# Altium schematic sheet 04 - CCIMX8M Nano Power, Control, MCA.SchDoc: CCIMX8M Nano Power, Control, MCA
size A3; PageSetup: Record=PageOptions¦CenterHorizontal=True¦CenterVertical=True¦PrintScale=0.70¦XCorrection=1.00¦YCorrection=1.00¦PrintKind=0¦BorderSize=5000000¦LeftOffset=0¦BottomOffset=0¦Orientation=2¦PaperLength=4200¦PaperWidth=2970¦Scale=100¦PaperSource=7¦PrintQuality=600¦MediaType=1¦DitherType=10¦PaperKind=A4¦PrintScaleMode=1; Author: Juan Anzola; SheetNumber: 4; SheetTotal: 21
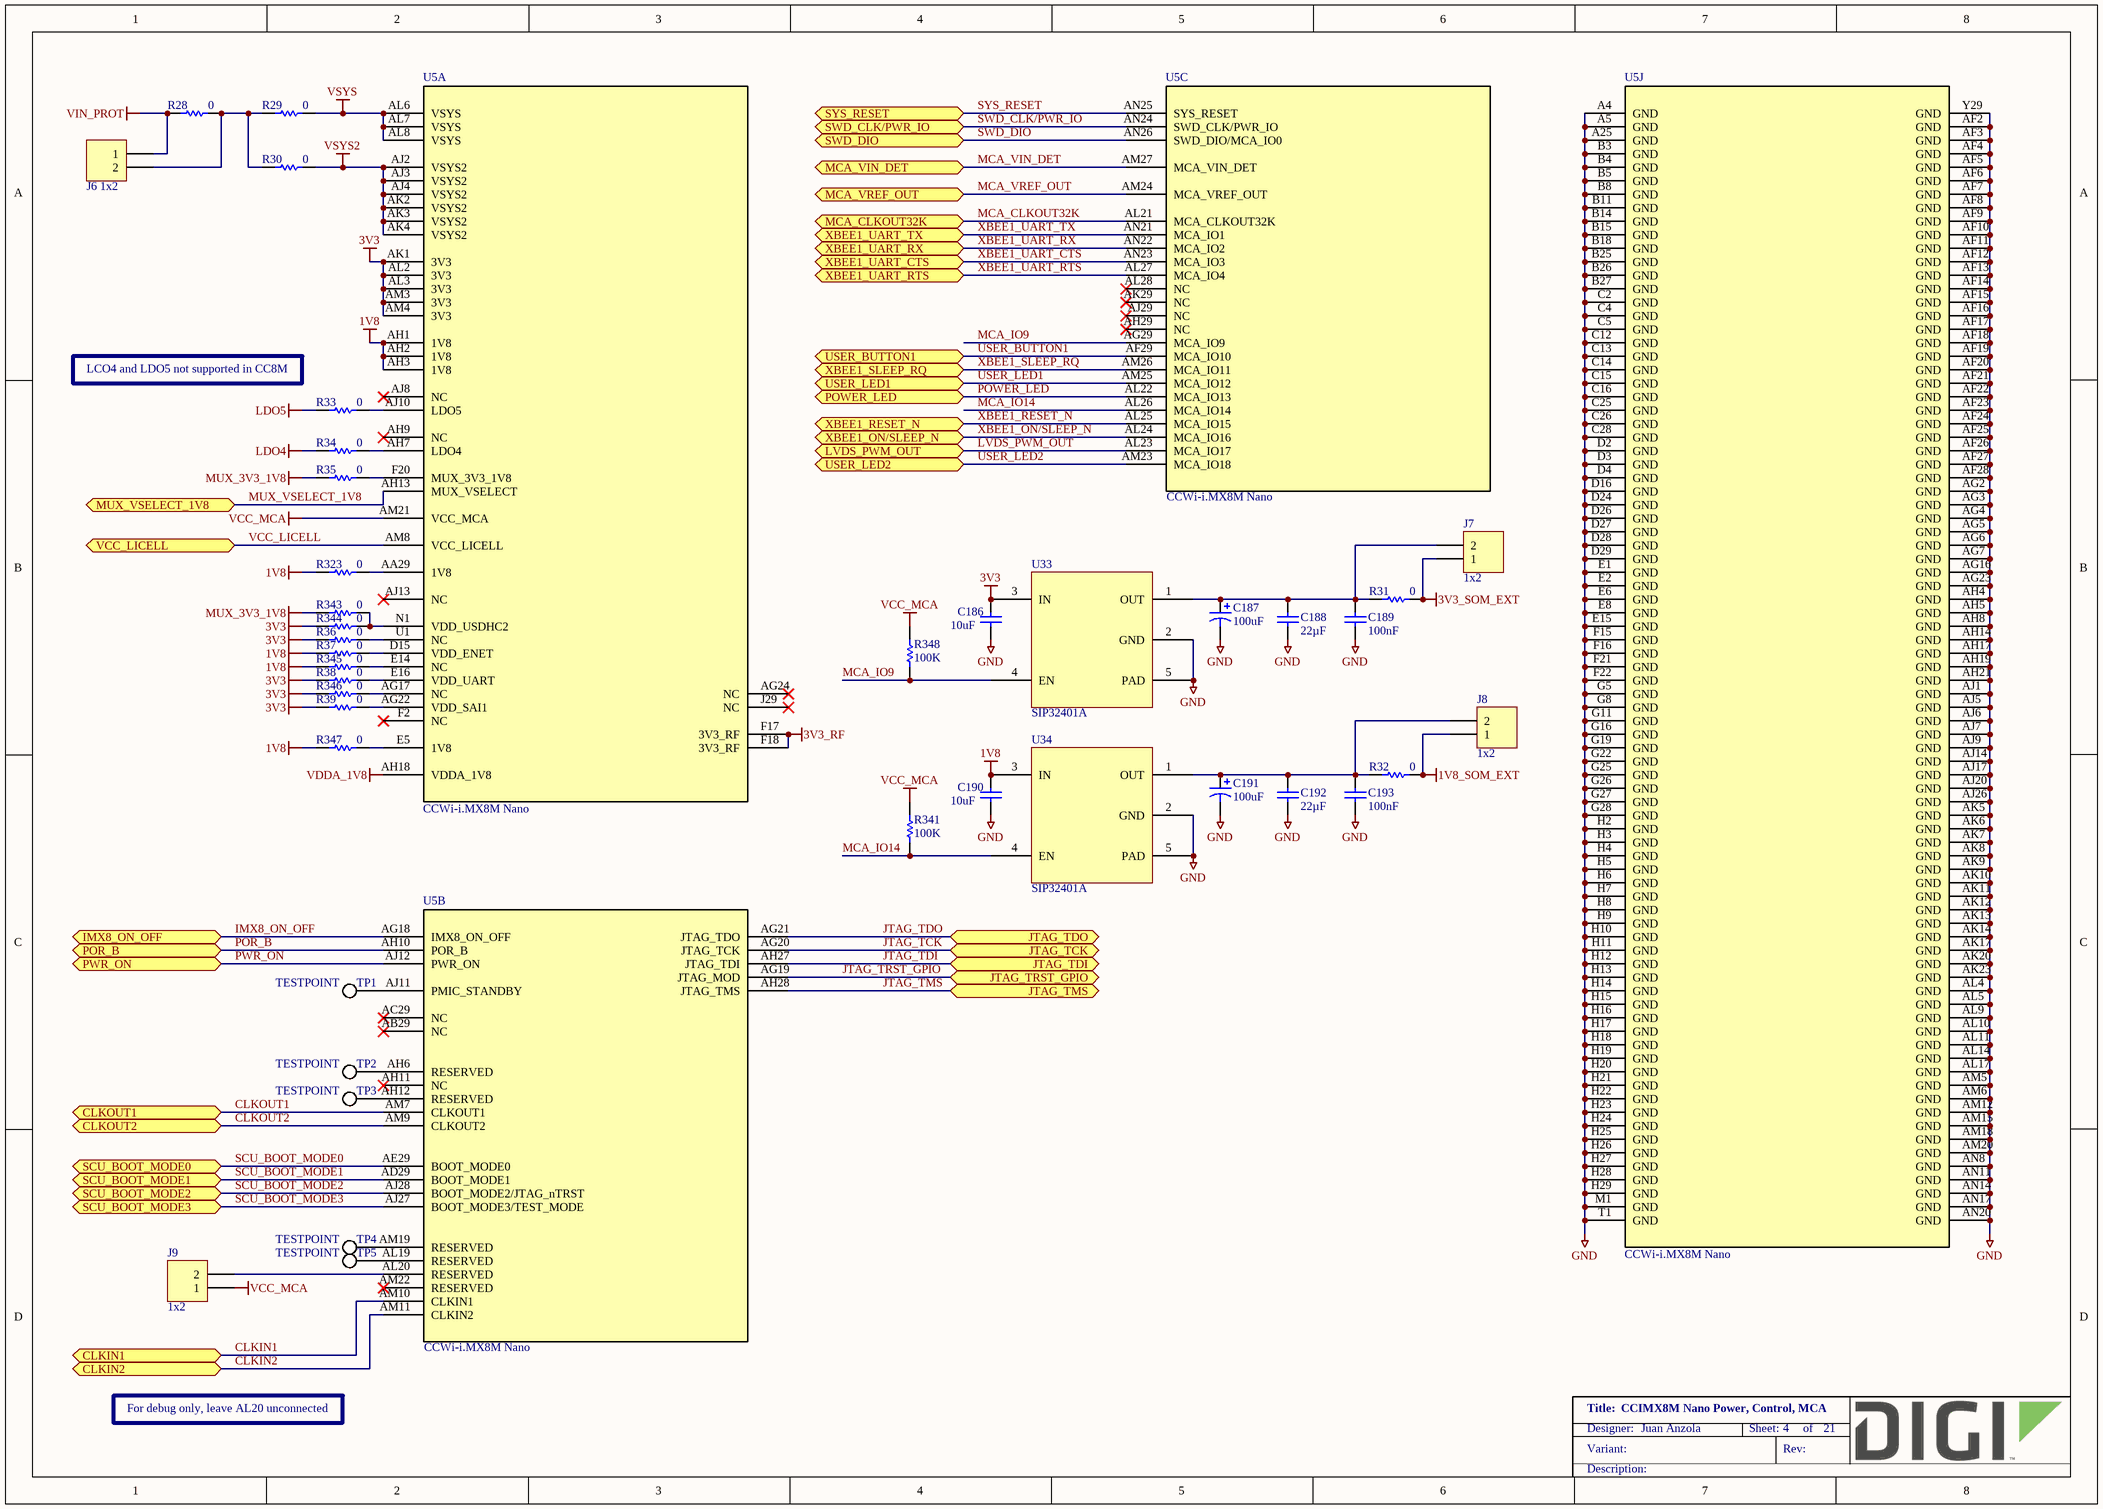
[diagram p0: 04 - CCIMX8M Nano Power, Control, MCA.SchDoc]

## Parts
C186  10uF  [CAPC1005X55N]
C187  100uF  [CAPMP3216X120N]
C188  22µF  [CAPC1608X90N]
C189  100nF  [CAPC1005X55N]
C190  10uF  [CAPC1005X55N]
C191  100uF  [CAPMP3216X120N]
C192  22µF  [CAPC1608X90N]
C193  100nF  [CAPC1005X55N]
J6  1x2  [FCI_68002-102HLF]
J7  1x2  [FCI_68002-102HLF]
J8  1x2  [FCI_68002-102HLF]
J9  1x2  [FCI_68002-102HLF]
R28  0  [RESC1609X55N]
R29  0  [RESC1609X55N]
R30  0  [RESC1609X55N]
R31  0  [RESC1609X55N]
R32  0  [RESC1609X55N]
R33  0  [RESC1609X55N]
R34  0  [RESC1609X55N]
R35  0  [RESC1609X55N]
R36  0  [RESC1005X40N]
R37  0  [RESC1005X40N]
R38  0  [RESC1005X40N]
R39  0  [RESC1005X40N]
R323  0  [RESC1005X40N]
R341  100K  [RESC1005X40N]
R343  0  [RESC1005X40N]
R344  0  [RESC1005X40N]
R345  0  [RESC1005X40N]
R346  0  [RESC1005X40N]
R347  0  [RESC1005X40N]
R348  100K  [RESC1005X40N]
TP1  TESTPOINT  [TP0762]  (no BOM)
TP2  TESTPOINT  [TP0762]  (no BOM)
TP3  TESTPOINT  [TP0762]  (no BOM)
TP4  TESTPOINT  [TP0762]  (no BOM)
TP5  TESTPOINT  [TP0762]  (no BOM)
U5  CCWi-i.MX8M Nano  [E-TEC_LPJ474-129M-32ABEW55L]  (parts A,B,C,J of 10)
U33  SIP32401A  [SON50P120X160X60-5T55X91N]
U34  SIP32401A  [SON50P120X160X60-5T55X91N]

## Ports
CLKIN1 (bidir), CLKIN2 (bidir), CLKOUT1 (bidir), CLKOUT2 (bidir), IMX8_ON_OFF (bidir), JTAG_TCK (bidir), JTAG_TDI (bidir), JTAG_TDO (bidir), JTAG_TMS (bidir), JTAG_TRST_GPIO (bidir), LVDS_PWM_OUT (bidir), MCA_CLKOUT32K (bidir), MCA_VIN_DET (bidir), MCA_VREF_OUT (bidir), MUX_VSELECT_1V8 (bidir), POR_B (bidir), POWER_LED (bidir), PWR_ON (bidir), SCU_BOOT_MODE0 (bidir), SCU_BOOT_MODE1 (bidir), SCU_BOOT_MODE2 (bidir), SCU_BOOT_MODE3 (bidir), SWD_CLK/PWR_IO (bidir), SWD_DIO (bidir), SYS_RESET (bidir), USER_BUTTON1 (bidir), USER_LED1 (bidir), USER_LED2 (bidir), VCC_LICELL (bidir), XBEE1_ON/SLEEP_N (bidir), XBEE1_RESET_N (bidir), XBEE1_SLEEP_RQ (bidir), XBEE1_UART_CTS (bidir), XBEE1_UART_RTS (bidir), XBEE1_UART_RX (bidir), XBEE1_UART_TX (bidir)

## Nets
1V8: C190.2 R37.1 R323.1 R345.1 R347.1 U5.AH1(1V8) U5.AH2(1V8) U5.AH3(1V8) U34.3(IN)
1V8_SOM_EXT: J8.1 R32.2
3V3: C186.2 R36.1 R38.1 R39.1 R344.1 R346.1 U5.AK1(3V3) U5.AL2(3V3) U5.AL3(3V3) U5.AM3(3V3) U5.AM4(3V3) U33.3(IN)
3V3_RF: U5.F17(3V3_RF) U5.F18(3V3_RF)
3V3_SOM_EXT: J7.1 R31.2
GND: C186.1 C187.2 C188.1 C189.1 C190.1 C191.2 C192.1 C193.1 U5.A25(GND) U5.A4(GND) U5.A5(GND) U5.AF2(GND) U5.AF3(GND) U5.AF4(GND) U5.AF5(GND) U5.AF6(GND) U5.AF7(GND) U5.AF8(GND) U5.AF9(GND) U5.AF10(GND) U5.AF11(GND) U5.AF12(GND) U5.AF13(GND) U5.AF14(GND) U5.AF15(GND) U5.AF16(GND) U5.AF17(GND) U5.AF18(GND) U5.AF19(GND) U5.AF20(GND) U5.AF21(GND) U5.AF22(GND) U5.AF23(GND) U5.AF24(GND) U5.AF25(GND) U5.AF26(GND) U5.AF27(GND) U5.AF28(GND) U5.AG2(GND) U5.AG3(GND) U5.AG4(GND) U5.AG5(GND) U5.AG6(GND) U5.AG7(GND) U5.AG16(GND) U5.AG23(GND) U5.AH4(GND) U5.AH5(GND) U5.AH8(GND) U5.AH14(GND) U5.AH17(GND) U5.AH19(GND) U5.AH21(GND) U5.AJ1(GND) U5.AJ5(GND) U5.AJ6(GND) U5.AJ7(GND) U5.AJ9(GND) U5.AJ14(GND) U5.AJ17(GND) U5.AJ20(GND) U5.AJ26(GND) U5.AK5(GND) U5.AK6(GND) U5.AK7(GND) U5.AK8(GND) U5.AK9(GND) U5.AK10(GND) U5.AK11(GND) U5.AK12(GND) U5.AK13(GND) U5.AK14(GND) U5.AK17(GND) U5.AK20(GND) U5.AK23(GND) U5.AL4(GND) U5.AL5(GND) U5.AL9(GND) U5.AL10(GND) U5.AL11(GND) U5.AL14(GND) U5.AL17(GND) U5.AM5(GND) U5.AM6(GND) U5.AM12(GND) U5.AM15(GND) U5.AM18(GND) U5.AM20(GND) U5.AN8(GND) U5.AN11(GND) U5.AN14(GND) U5.AN17(GND) U5.AN20(GND) U5.B3(GND) U5.B4(GND) U5.B5(GND) U5.B8(GND) U5.B11(GND) U5.B14(GND) U5.B15(GND) U5.B18(GND) U5.B25(GND) U5.B26(GND) U5.B27(GND) U5.C2(GND) U5.C4(GND) U5.C5(GND) U5.C12(GND) U5.C13(GND) U5.C14(GND) U5.C15(GND) U5.C16(GND) U5.C25(GND) U5.C26(GND) U5.C28(GND) U5.D2(GND) U5.D3(GND) U5.D4(GND) U5.D16(GND) U5.D24(GND) U5.D26(GND) U5.D27(GND) U5.D28(GND) U5.D29(GND) U5.E1(GND) U5.E2(GND) U5.E6(GND) U5.E8(GND) U5.E15(GND) U5.F15(GND) U5.F16(GND) U5.F21(GND) U5.F22(GND) U5.G5(GND) U5.G8(GND) U5.G11(GND) U5.G16(GND) U5.G19(GND) U5.G22(GND) U5.G25(GND) U5.G26(GND) U5.G27(GND) U5.G28(GND) U5.H2(GND) U5.H3(GND) U5.H4(GND) U5.H5(GND) U5.H6(GND) U5.H7(GND) U5.H8(GND) U5.H9(GND) U5.H10(GND) U5.H11(GND) U5.H12(GND) U5.H13(GND) U5.H14(GND) U5.H15(GND) U5.H16(GND) U5.H17(GND) U5.H18(GND) U5.H19(GND) U5.H20(GND) U5.H21(GND) U5.H22(GND) U5.H23(GND) U5.H24(GND) U5.H25(GND) U5.H26(GND) U5.H27(GND) U5.H28(GND) U5.H29(GND) U5.M1(GND) U5.T1(GND) U5.Y29(GND) U33.2(GND) U33.5(PAD) U34.2(GND) U34.5(PAD)
LDO4: R34.1
LDO5: R33.1
MUX_3V3_1V8: R35.1 R343.1
VCC_MCA: J9.1 R341.2 R348.2 U5.AM21(VCC_MCA)
VDDA_1V8: U5.AH18(VDDA_1V8)
VIN_PROT: J6.1 R28.1
VSYS: R29.2 U5.AL6(VSYS) U5.AL7(VSYS) U5.AL8(VSYS)
VSYS2: R30.2 U5.AJ2(VSYS2) U5.AJ3(VSYS2) U5.AJ4(VSYS2) U5.AK2(VSYS2) U5.AK3(VSYS2) U5.AK4(VSYS2)
CLKIN1: U5.AM10(CLKIN1) ; port CLKIN1
CLKIN2: U5.AM11(CLKIN2) ; port CLKIN2
CLKOUT1: U5.AM7(CLKOUT1) ; port CLKOUT1
CLKOUT2: U5.AM9(CLKOUT2) ; port CLKOUT2
IMX8_ON_OFF: U5.AG18(IMX8_ON_OFF) ; port IMX8_ON_OFF
JTAG_TCK: U5.AG20(JTAG_TCK) ; port JTAG_TCK
JTAG_TDI: U5.AH27(JTAG_TDI) ; port JTAG_TDI
JTAG_TDO: U5.AG21(JTAG_TDO) ; port JTAG_TDO
JTAG_TMS: U5.AH28(JTAG_TMS) ; port JTAG_TMS
JTAG_TRST_GPIO: U5.AG19(JTAG_MOD) ; port JTAG_TRST_GPIO
LVDS_PWM_OUT: U5.AL23(MCA_IO17) ; port LVDS_PWM_OUT
MCA_CLKOUT32K: U5.AL21(MCA_CLKOUT32K) ; port MCA_CLKOUT32K
MCA_IO9: R348.1 U5.AG29(MCA_IO9) U33.4(EN)
MCA_IO14: R341.1 U5.AL26(MCA_IO14) U34.4(EN)
MCA_VIN_DET: U5.AM27(MCA_VIN_DET) ; port MCA_VIN_DET
MCA_VREF_OUT: U5.AM24(MCA_VREF_OUT) ; port MCA_VREF_OUT
MUX_VSELECT_1V8: U5.AH13(MUX_VSELECT) ; port MUX_VSELECT_1V8
POR_B: U5.AH10(POR_B) ; port POR_B
POWER_LED: U5.AL22(MCA_IO13) ; port POWER_LED
PWR_ON: U5.AJ12(PWR_ON) ; port PWR_ON
SCU_BOOT_MODE0: U5.AE29(BOOT_MODE0) ; port SCU_BOOT_MODE0
SCU_BOOT_MODE1: U5.AD29(BOOT_MODE1) ; port SCU_BOOT_MODE1
SCU_BOOT_MODE2: U5.AJ28(BOOT_MODE2/JTAG_nTRST) ; port SCU_BOOT_MODE2
SCU_BOOT_MODE3: U5.AJ27(BOOT_MODE3/TEST_MODE) ; port SCU_BOOT_MODE3
SWD_CLK/PWR_IO: U5.AN24(SWD_CLK/PWR_IO) ; port SWD_CLK/PWR_IO
SWD_DIO: U5.AN26(SWD_DIO/MCA_IO0) ; port SWD_DIO
SYS_RESET: U5.AN25(SYS_RESET) ; port SYS_RESET
USER_BUTTON1: U5.AF29(MCA_IO10) ; port USER_BUTTON1
USER_LED1: U5.AM25(MCA_IO12) ; port USER_LED1
USER_LED2: U5.AM23(MCA_IO18) ; port USER_LED2
VCC_LICELL: U5.AM8(VCC_LICELL) ; port VCC_LICELL
XBEE1_ON/SLEEP_N: U5.AL24(MCA_IO16) ; port XBEE1_ON/SLEEP_N
XBEE1_RESET_N: U5.AL25(MCA_IO15) ; port XBEE1_RESET_N
XBEE1_SLEEP_RQ: U5.AM26(MCA_IO11) ; port XBEE1_SLEEP_RQ
XBEE1_UART_CTS: U5.AN23(MCA_IO3) ; port XBEE1_UART_CTS
XBEE1_UART_RTS: U5.AL27(MCA_IO4) ; port XBEE1_UART_RTS
XBEE1_UART_RX: U5.AN22(MCA_IO2) ; port XBEE1_UART_RX
XBEE1_UART_TX: U5.AN21(MCA_IO1) ; port XBEE1_UART_TX
NetC187_1: C187.1 C188.2 C189.2 J7.2 R31.1 U33.1(OUT)
NetC191_1: C191.1 C192.2 C193.2 J8.2 R32.1 U34.1(OUT)
NetJ6_2: J6.2 R28.2 R29.1 R30.1
NetJ9_2: J9.2 U5.AL20(RESERVED)
NetR33_2: R33.2 U5.AJ10(LDO5)
NetR34_2: R34.2 U5.AH7(LDO4)
NetR35_2: R35.2 U5.F20(MUX_3V3_1V8)
NetR36_2: R36.2 U5.U1(NC)
NetR37_2: R37.2 U5.D15(VDD_ENET)
NetR38_2: R38.2 U5.E16(VDD_UART)
NetR39_2: R39.2 U5.AG22(VDD_SAI1)
NetR323_2: R323.2 U5.AA29(1V8)
NetR343_2: R343.2 R344.2 U5.N1(VDD_USDHC2)
NetR345_2: R345.2 U5.E14(NC)
NetR346_2: R346.2 U5.AG17(NC)
NetR347_2: R347.2 U5.E5(1V8)
NetTP1_1: TP1.1 U5.AJ11(PMIC_STANDBY)
NetTP2_1: TP2.1 U5.AH6(RESERVED)
NetTP3_1: TP3.1 U5.AH12(RESERVED)
NetTP4_1: TP4.1 U5.AM19(RESERVED)
NetTP5_1: TP5.1 U5.AL19(RESERVED)

Not connected (* = marked no-connect by the designer): U5 AB29(NC)* AC29(NC)* AG24(NC)* AH9(NC)* AH11(NC)* AH29(NC)* AJ8(NC)* AJ13(NC)* AJ29(NC)* AK29(NC)* AL28(NC)* AM22(RESERVED)* F2(NC)* J29(NC)*

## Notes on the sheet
- (near R33) LCO4 and LDO5 not supported in CC8M
- For debug only, leave AL20 unconnected

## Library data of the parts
C186 C190 = 1001168: CAP CER 10UF 10V 20% X5R 0402; Part_Type: Capacitor; Manufacturer: Samsung; Manufacturer_Part_Number: CL05A106MP5NUNC; Digi_PN: 14050689; Component_Life_Cycle_State: Reviewed; Area: 0.95; Project: CCWMX6_SBC board
C187 C191 = 1001196: CAP TANT 100UF 6.3V 20% 1206; Part_Type: Capacitor; Manufacturer: Rohm; Manufacturer_Part_Number: TCTAL0J107M8R; Digi_PN: 14050490; Component_Life_Cycle_State: Reviewed; Area: 8.01; Project: CCWMX6_SBC board
C188 C192 = 1000998: CAP CER 22UF 10V 20% X5R 0603; Part_Type: Capacitor; Manufacturer: Samsung; Manufacturer_Part_Number: CL10A226MP8NUNE; Manufacturer_Alt_1: TDK Corporation; Manufacturer_Alt_1_Part_Number: C1608X5R1A226M080AC; Digi_PN: 14050684; Component_Life_Cycle_State: Reviewed; Area: 2.27; Project: ConnectCore i.MX6 module; Tolerance: 20
C189 C193 = 1000006: CAP 100nF 16V 10% X7R 0402; Part_Type: Capacitor; Manufacturer: Murata; Manufacturer_Part_Number: GRM155R71C104KA88D; Component_Life_Cycle_State: CAD Reviewed; Area: 0.95; Project: KITT; Tolerance: 10; Digi_PN: 14050552
J6-J9 = 1001128: CONN HEADER 2POS .100" SGL GOLD; Part_Type: Connector; Manufacturer: Samtec; Manufacturer_Part_Number: TSW-102-07-G-S; Digi_PN: 00120002; Component_Life_Cycle_State: Reviewed; Area: 12,9032
R28 = 1000208: RES 0.0 OHM 1/10W 0603; Part_Type: Resistor; Manufacturer: Panasonic - ECG; Manufacturer_Part_Number: ERJ-3GEY0R00V; Note: 13051103 = Digi No. for GE WDNU; Digi_PN: 13050568; Component_Life_Cycle_State: Reviewed; Area: 2,5; Voltage: 75V
R29-R35 = 1000208: RES 0.0 OHM 1/10W 0603; Part_Type: Resistor; Manufacturer: Panasonic - ECG; Manufacturer_Part_Number: ERJ-3GEY0R00V; Note: 13051103 = Digi No. for GE WDNU; Digi_PN: 13050568; Component_Life_Cycle_State: Reviewed; Area: 2,5; Project: Adjustable Foundation; Voltage: 75V
R36-R39 R323 = 1000076: RES 0.0 OHM 1/10W 0402 SMD; Part_Type: Resistor; Manufacturer: Panasonic - ECG; Manufacturer_Part_Number: ERJ-2GE0R00X; Digi_PN: 13050387; Component_Life_Cycle_State: Proven; Area: 0,95; Project: Adjustable Foundation; Power_WV_SRF: 10
R341 R348 = 1000480: RES 100K OHM 1/10W 1% 0402 SMD; Part_Type: Resistor; Manufacturer: Panasonic - ECG; Manufacturer_Part_Number: ERJ-2RKF1003X; Digi_PN: 13051063; Component_Life_Cycle_State: CAD Reviewed; Area: 0.95; Project: KITT; Power_WV_SRF: 100
R343-R347 = 1000076: RES 0.0 OHM 1/10W 0402 SMD; Part_Type: Resistor; Manufacturer: Panasonic - ECG; Manufacturer_Part_Number: ERJ-2GE0R00X; Digi_PN: 13050387; Component_Life_Cycle_State: Proven; Area: 0,95; Power_WV_SRF: 10
TP1-TP5 = CAD0011: TEST POINT 30MIL PAD SMT; Component_Life_Cycle_State: Reviewed; Area: 0,58; Project: CLC
U5 = 1002739: ConnectCore for i.MX8M Nano module - LGA; Manufacturer: DIGI; Digi_PN: 50002014-01; Component_Life_Cycle_State: Pending
U33 U34 = 1001857: IC SW W/CTRL SLEW RATE 4TDFN; Manufacturer: Vishay Siliconix; Manufacturer_Part_Number: SIP32401ADNP-T1GE4; Component_Life_Cycle_State: Reviewed; Area: 4.93; Project: CCWMX6_SBC board; Digi_PN: 16052004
